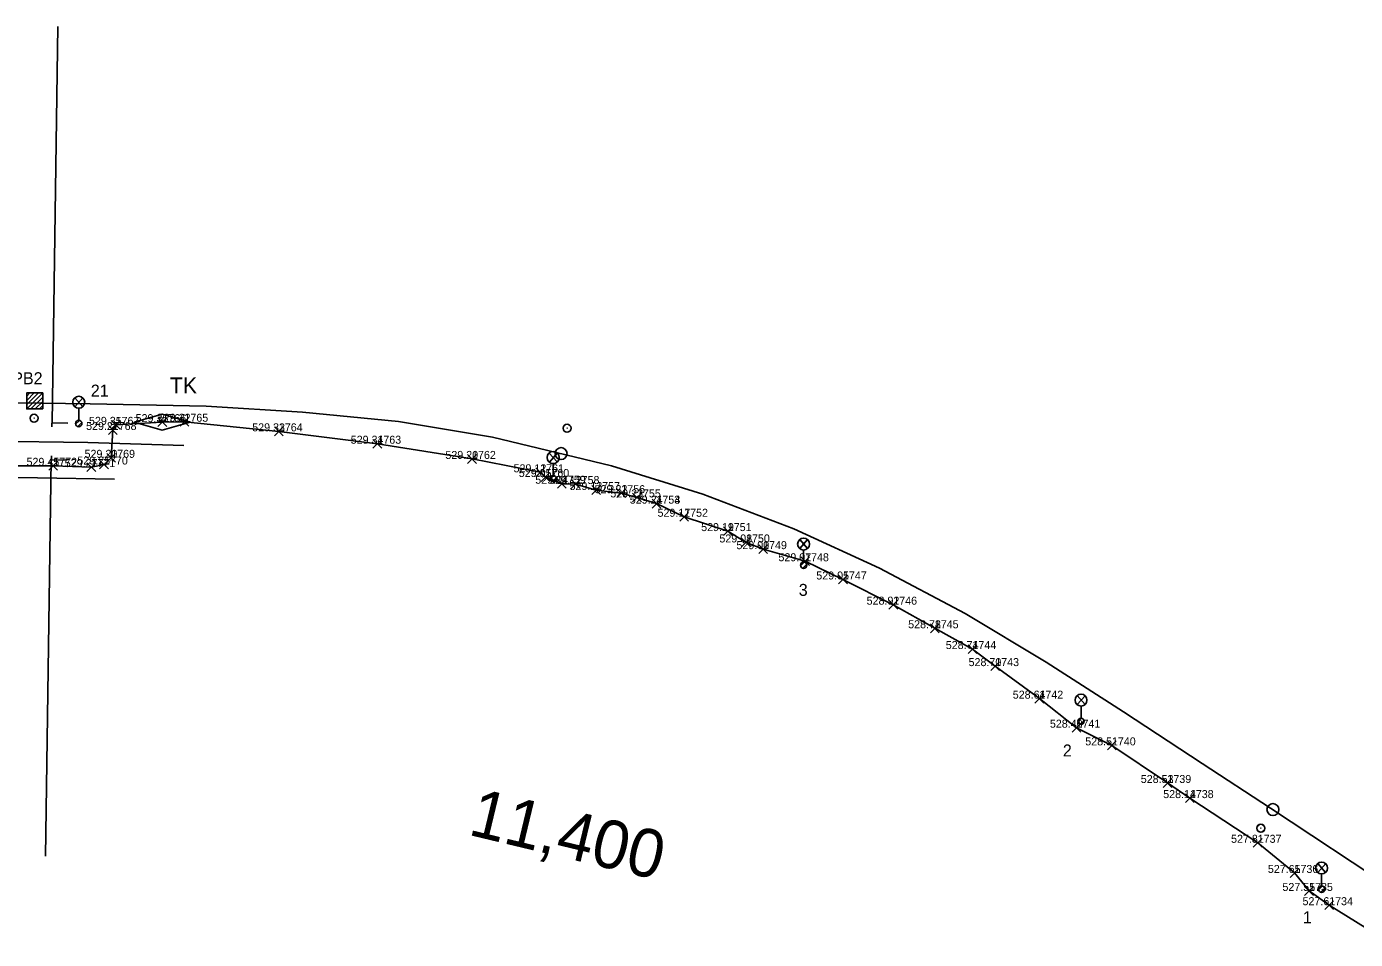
# Model space of a CAD drawing. Extents: x -874058 to -854960, y -10531873 to -1049126.
# Drawn here: x -873748.8 to -873582.7, y -1055503.4 to -1055389.3 of the extents above; entities that cross this region are included whole.
import ezdxf

# ---------------------------------------------------------------- set-up
doc = ezdxf.new("R2010")
doc.units = 0
for name, color, linetype in [('Vrstva 1', 7, 'Continuous'), ('Vrstva 25', 7, 'Continuous'), ('Vrstva 3', 7, 'Continuous'), ('Vrstva 32', 7, 'Continuous'), ('Vrstva 35', 7, 'Continuous'), ('Vrstva 50', 7, 'Continuous'), ('Vrstva 6', 7, 'Continuous'), ('Vrstva 60', 7, 'Continuous'), ('Vrstva 61', 7, 'Continuous'), ('Vrstva 7', 7, 'Continuous')]:
    doc.layers.add(name, color=color, linetype=linetype)

msp = doc.modelspace()

# ---------------------------------------------------------------- linework, layer by layer
at = {"layer": 'Vrstva 1'}
for points in [[(-873927.58, -1055424.84), (-873900.45, -1055425.31), (-873892.13, -1055425.7), (-873880.59, -1055426.63), (-873873.55, -1055427.3), (-873854.79, -1055429.58), (-873843.62, -1055431.39), (-873833.71, -1055432.56), (-873816.9, -1055434.47), (-873807.04, -1055435.55), (-873783.51, -1055438.28), (-873772.32, -1055439.75), (-873753.41, -1055441.11), (-873741.16, -1055441.25), (-873729.15, -1055441.64)], [(-873577.97, -1055497.15), (-873593.34, -1055486.97), (-873601.88, -1055481.39), (-873611.75, -1055474.94), (-873621.41, -1055468.71), (-873631.51, -1055462.63), (-873642.21, -1055456.97), (-873652.94, -1055452.07), (-873664.28, -1055447.72), (-873675.71, -1055444.17), (-873690.6, -1055440.6), (-873702.33, -1055438.64), (-873714.32, -1055437.46), (-873726.38, -1055436.71), (-873740.86, -1055436.45), (-873753.23, -1055436.27)], [(-873737.8, -1055445.87), (-873747.46, -1055445.67), (-873767.6, -1055445.41), (-873858.85, -1055444.62), (-873898.81, -1055444.08), (-873934.67, -1055443.63), (-873987.18, -1055443.07), (-874021.63, -1055442.79), (-874051.6, -1055442.39)]]:
    msp.add_lwpolyline(points, dxfattribs=at)
at = {"layer": 'Vrstva 25'}
for p, q in [((-873742.78, -1055435.68), (-873741.79, -1055436.79)), ((-873742.77, -1055436.81), (-873741.79, -1055435.69)), ((-873742.68, -1055438.97), (-873742.21, -1055438.5)), ((-873742.29, -1055436.99), (-873742.29, -1055438.49)), ((-873742.41, -1055439.27), (-873741.91, -1055438.77)), ((-873683.49, -1055442.58), (-873682.5, -1055443.7)), ((-873683.48, -1055443.71), (-873682.49, -1055442.59)), ((-873683, -1055443.89), (-873683, -1055445.39)), ((-873683.39, -1055445.87), (-873682.92, -1055445.4)), ((-873683.12, -1055446.17), (-873682.62, -1055445.67)), ((-873652.19, -1055453.4), (-873651.2, -1055454.52)), ((-873652.18, -1055454.53), (-873651.2, -1055453.41)), ((-873651.7, -1055454.71), (-873651.7, -1055456.21)), ((-873652.09, -1055456.69), (-873651.62, -1055456.22)), ((-873651.82, -1055456.99), (-873651.32, -1055456.49)), ((-873617.53, -1055472.91), (-873616.54, -1055474.03)), ((-873617.52, -1055474.04), (-873616.54, -1055472.92)), ((-873617.04, -1055474.22), (-873617.04, -1055475.72)), ((-873617.43, -1055476.2), (-873616.96, -1055475.73)), ((-873617.16, -1055476.5), (-873616.66, -1055476)), ((-873587.46, -1055493.9), (-873586.47, -1055495.02)), ((-873587.45, -1055495.03), (-873586.46, -1055493.91)), ((-873586.97, -1055495.21), (-873586.97, -1055496.71)), ((-873587.36, -1055497.19), (-873586.89, -1055496.72)), ((-873587.09, -1055497.49), (-873586.59, -1055496.99))]:
    msp.add_line(p, q, dxfattribs=at)
for centre, radius in [((-873742.29, -1055436.24), 0.749), ((-873742.29, -1055438.89), 0.4), ((-873742.29, -1055438.89), 0.4), ((-873683, -1055443.14), 0.749), ((-873683, -1055445.79), 0.4), ((-873683, -1055445.79), 0.4), ((-873651.7, -1055453.96), 0.749), ((-873651.7, -1055456.61), 0.4), ((-873651.7, -1055456.61), 0.4), ((-873617.04, -1055473.47), 0.749), ((-873617.04, -1055476.12), 0.4), ((-873617.04, -1055476.12), 0.4), ((-873586.97, -1055494.46), 0.749), ((-873586.97, -1055497.11), 0.4), ((-873586.97, -1055497.11), 0.4)]:
    msp.add_circle(centre, radius, dxfattribs=at)
at = {"layer": 'Vrstva 3'}
for p, q in [((-873746.79, -1055435.06), (-873748.79, -1055437.06)), ((-873747.32, -1055435.06), (-873748.79, -1055436.53)), ((-873747.85, -1055435.06), (-873748.79, -1055436)), ((-873748.38, -1055435.06), (-873748.79, -1055435.47)), ((-873746.79, -1055435.59), (-873748.26, -1055437.06)), ((-873746.79, -1055436.12), (-873747.73, -1055437.06)), ((-873746.79, -1055436.65), (-873747.2, -1055437.06))]:
    msp.add_line(p, q, dxfattribs=at)
msp.add_lwpolyline([(-873746.79, -1055437.06), (-873748.79, -1055437.06), (-873748.79, -1055435.06), (-873746.79, -1055435.06)], close=True, dxfattribs=at)
msp.add_lwpolyline([(-873746.79, -1055437.06), (-873748.79, -1055437.06), (-873748.79, -1055435.06), (-873746.79, -1055435.06)], close=True, dxfattribs=at)
msp.add_lwpolyline([(-873746.79, -1055437.06), (-873748.79, -1055437.06), (-873748.79, -1055435.06), (-873746.79, -1055435.06), (-873746.79, -1055437.06)], dxfattribs=at)
msp.add_lwpolyline([(-873746.79, -1055437.06), (-873748.79, -1055437.06), (-873748.79, -1055435.06), (-873746.79, -1055435.06), (-873746.79, -1055437.06)], dxfattribs=at)
at = {"layer": 'Vrstva 32'}
for points in [[(-873735.35, -1055438.72), (-873731.85, -1055437.72), (-873728.35, -1055438.72), (-873731.85, -1055439.72), (-873735.35, -1055438.72)], [(-873751.74, -1055444.2), (-873745.48, -1055444.18), (-873740.71, -1055444.34), (-873739.13, -1055444.02), (-873738.23, -1055443.18), (-873738.04, -1055439.7), (-873737.68, -1055439.06), (-873731.85, -1055438.72), (-873729.08, -1055438.67), (-873717.28, -1055439.87), (-873704.97, -1055441.42), (-873693.14, -1055443.32), (-873684.62, -1055444.99), (-873683.97, -1055445.58), (-873681.91, -1055446.42), (-873680.19, -1055446.46), (-873677.63, -1055447.21), (-873674.49, -1055447.6), (-873672.53, -1055448.13), (-873670.1, -1055448.91)], [(-873579.12, -1055503.39), (-873586.03, -1055499.11), (-873588.54, -1055497.33), (-873590.36, -1055495.08), (-873594.96, -1055491.31), (-873603.44, -1055485.72), (-873606.24, -1055483.83), (-873613.18, -1055479.13), (-873617.6, -1055476.92), (-873622.24, -1055473.29), (-873627.76, -1055469.22), (-873630.61, -1055467.09), (-873635.31, -1055464.49), (-873640.5, -1055461.54), (-873646.79, -1055458.39), (-873651.52, -1055456.11), (-873656.77, -1055454.6), (-873658.9, -1055453.76), (-873661.18, -1055452.34), (-873666.63, -1055450.55), (-873670.1, -1055448.91)]]:
    msp.add_lwpolyline(points, dxfattribs=at)
at = {"layer": 'Vrstva 35'}
msp.add_lwpolyline([(-873738.23, -1055443.18), (-873738.04, -1055439.7)], dxfattribs=at)
at = {"layer": 'Vrstva 50'}
msp.add_line((-873747.92, -1055438.23), (-873747.82, -1055438.23), dxfattribs=at)
msp.add_circle((-873747.87, -1055438.23), 0.5, dxfattribs=at)
at = {"layer": 'Vrstva 6'}
for p, q in [((-873744.9, -1055389.27), (-873745.62, -1055438.79)), ((-873745.61, -1055438.29), (-873745.63, -1055439.29)), ((-873743.64, -1055438.84), (-873745.62, -1055438.79)), ((-873745.72, -1055443.44), (-873746.44, -1055492.96)), ((-873745.71, -1055442.94), (-873745.73, -1055443.94)), ((-873743.74, -1055443.49), (-873745.72, -1055443.44))]:
    msp.add_line(p, q, dxfattribs=at)
at = {"layer": 'Vrstva 60'}
for p, q in [((-873738.23, -1055439.61), (-873737.13, -1055438.51)), ((-873737.13, -1055439.61), (-873738.23, -1055438.51)), ((-873732.4, -1055439.27), (-873731.3, -1055438.17)), ((-873731.3, -1055439.27), (-873732.4, -1055438.17)), ((-873729.63, -1055439.22), (-873728.53, -1055438.12)), ((-873728.53, -1055439.22), (-873729.63, -1055438.12)), ((-873738.59, -1055440.25), (-873737.49, -1055439.15)), ((-873737.49, -1055440.25), (-873738.59, -1055439.15)), ((-873717.83, -1055440.42), (-873716.73, -1055439.32)), ((-873716.73, -1055440.42), (-873717.83, -1055439.32)), ((-873705.52, -1055441.97), (-873704.42, -1055440.87)), ((-873704.42, -1055441.97), (-873705.52, -1055440.87)), ((-873739.68, -1055444.57), (-873738.58, -1055443.47)), ((-873738.58, -1055444.57), (-873739.68, -1055443.47)), ((-873738.78, -1055443.73), (-873737.68, -1055442.63)), ((-873737.68, -1055443.73), (-873738.78, -1055442.63)), ((-873693.69, -1055443.87), (-873692.59, -1055442.77)), ((-873692.59, -1055443.87), (-873693.69, -1055442.77)), ((-873746.03, -1055444.73), (-873744.93, -1055443.63)), ((-873744.93, -1055444.73), (-873746.03, -1055443.63)), ((-873741.26, -1055444.89), (-873740.16, -1055443.79)), ((-873740.16, -1055444.89), (-873741.26, -1055443.79)), ((-873685.17, -1055445.54), (-873684.07, -1055444.44)), ((-873684.07, -1055445.54), (-873685.17, -1055444.44)), ((-873684.52, -1055446.13), (-873683.42, -1055445.03)), ((-873683.42, -1055446.13), (-873684.52, -1055445.03)), ((-873682.46, -1055446.97), (-873681.36, -1055445.87)), ((-873681.36, -1055446.97), (-873682.46, -1055445.87)), ((-873680.74, -1055447.01), (-873679.64, -1055445.91)), ((-873679.64, -1055447.01), (-873680.74, -1055445.91)), ((-873678.18, -1055447.76), (-873677.08, -1055446.66)), ((-873677.08, -1055447.76), (-873678.18, -1055446.66)), ((-873675.04, -1055448.15), (-873673.94, -1055447.05)), ((-873673.94, -1055448.15), (-873675.04, -1055447.05)), ((-873673.08, -1055448.68), (-873671.98, -1055447.58)), ((-873671.98, -1055448.68), (-873673.08, -1055447.58)), ((-873670.65, -1055449.46), (-873669.55, -1055448.36)), ((-873669.55, -1055449.46), (-873670.65, -1055448.36)), ((-873670.65, -1055449.46), (-873669.55, -1055448.36)), ((-873669.55, -1055449.46), (-873670.65, -1055448.36)), ((-873667.18, -1055451.1), (-873666.08, -1055450)), ((-873666.08, -1055451.1), (-873667.18, -1055450)), ((-873661.73, -1055452.89), (-873660.63, -1055451.79)), ((-873660.63, -1055452.89), (-873661.73, -1055451.79)), ((-873659.45, -1055454.31), (-873658.35, -1055453.21)), ((-873658.35, -1055454.31), (-873659.45, -1055453.21)), ((-873657.32, -1055455.15), (-873656.22, -1055454.05)), ((-873656.22, -1055455.15), (-873657.32, -1055454.05)), ((-873652.07, -1055456.66), (-873650.97, -1055455.56)), ((-873650.97, -1055456.66), (-873652.07, -1055455.56)), ((-873647.34, -1055458.94), (-873646.24, -1055457.84)), ((-873646.24, -1055458.94), (-873647.34, -1055457.84)), ((-873641.05, -1055462.09), (-873639.95, -1055460.99)), ((-873639.95, -1055462.09), (-873641.05, -1055460.99)), ((-873635.86, -1055465.04), (-873634.76, -1055463.94)), ((-873634.76, -1055465.04), (-873635.86, -1055463.94)), ((-873631.16, -1055467.64), (-873630.06, -1055466.54)), ((-873630.06, -1055467.64), (-873631.16, -1055466.54)), ((-873628.31, -1055469.77), (-873627.21, -1055468.67)), ((-873627.21, -1055469.77), (-873628.31, -1055468.67)), ((-873622.79, -1055473.84), (-873621.69, -1055472.74)), ((-873621.69, -1055473.84), (-873622.79, -1055472.74)), ((-873618.15, -1055477.47), (-873617.05, -1055476.37)), ((-873617.05, -1055477.47), (-873618.15, -1055476.37)), ((-873613.73, -1055479.68), (-873612.63, -1055478.58)), ((-873612.63, -1055479.68), (-873613.73, -1055478.58)), ((-873606.79, -1055484.38), (-873605.69, -1055483.28)), ((-873605.69, -1055484.38), (-873606.79, -1055483.28)), ((-873603.99, -1055486.27), (-873602.89, -1055485.17)), ((-873602.89, -1055486.27), (-873603.99, -1055485.17)), ((-873595.51, -1055491.86), (-873594.41, -1055490.76)), ((-873594.41, -1055491.86), (-873595.51, -1055490.76)), ((-873590.91, -1055495.63), (-873589.81, -1055494.53)), ((-873589.81, -1055495.63), (-873590.91, -1055494.53)), ((-873589.09, -1055497.88), (-873587.99, -1055496.78)), ((-873587.99, -1055497.88), (-873589.09, -1055496.78)), ((-873586.58, -1055499.66), (-873585.48, -1055498.56)), ((-873585.48, -1055499.66), (-873586.58, -1055498.56))]:
    msp.add_line(p, q, dxfattribs=at)
at = {"layer": 'Vrstva 7'}
for p, q in [((-873681.31, -1055439.48), (-873681.21, -1055439.48)), ((-873594.63, -1055489.48), (-873594.53, -1055489.48)), ((-873594.61, -1055489.49), (-873594.51, -1055489.49))]:
    msp.add_line(p, q, dxfattribs=at)
for centre, radius in [((-873681.26, -1055439.48), 0.5), ((-873682.02, -1055442.66), 0.75), ((-873593.05, -1055487.16), 0.75), ((-873594.58, -1055489.48), 0.5), ((-873594.56, -1055489.49), 0.5)]:
    msp.add_circle(centre, radius, dxfattribs=at)

# ---------------------------------------------------------------- texts
at = {"layer": 'Vrstva 25'}
for s, p in [('21', (-873740.78, -1055435.53)), ('3', (-873652.31, -1055460.44)), ('2', (-873619.31, -1055480.52)), ('1', (-873589.31, -1055501.37))]:
    msp.add_text(s, height=1.5, dxfattribs=at).set_placement(p)
at = {"layer": 'Vrstva 3'}
msp.add_text('TPB2', height=1.5, dxfattribs=at).set_placement((-873751.82, -1055433.98))
at = {"layer": 'Vrstva 32'}
msp.add_text('TK', height=2, dxfattribs=at).set_placement((-873730.92, -1055435.13))
at = {"layer": 'Vrstva 60'}
for s, p in [('1767', (-873737.68, -1055439.06)), ('1766', (-873731.85, -1055438.72)), ('1765', (-873729.08, -1055438.67)), ('1768', (-873738.04, -1055439.7)), ('1764', (-873717.28, -1055439.87)), ('1763', (-873704.97, -1055441.42)), ('1772', (-873745.48, -1055444.18)), ('1771', (-873740.71, -1055444.34)), ('1770', (-873739.13, -1055444.02)), ('1769', (-873738.23, -1055443.18)), ('1762', (-873693.14, -1055443.32)), ('1761', (-873684.62, -1055444.99)), ('1760', (-873683.97, -1055445.58)), ('1759', (-873681.91, -1055446.42)), ('1758', (-873680.19, -1055446.46)), ('1757', (-873677.63, -1055447.21)), ('1756', (-873674.49, -1055447.6)), ('1755', (-873672.53, -1055448.13)), ('1753', (-873670.1, -1055448.91)), ('1754', (-873670.1, -1055448.91)), ('1752', (-873666.63, -1055450.55)), ('1751', (-873661.18, -1055452.34)), ('1750', (-873658.9, -1055453.76)), ('1749', (-873656.77, -1055454.6)), ('1748', (-873651.52, -1055456.11)), ('1747', (-873646.79, -1055458.39)), ('1746', (-873640.5, -1055461.54)), ('1745', (-873635.31, -1055464.49)), ('1744', (-873630.61, -1055467.09)), ('1743', (-873627.76, -1055469.22)), ('1742', (-873622.24, -1055473.29)), ('1741', (-873617.6, -1055476.92)), ('1740', (-873613.18, -1055479.13)), ('1739', (-873606.24, -1055483.83)), ('1738', (-873603.44, -1055485.72)), ('1737', (-873594.96, -1055491.31)), ('1736', (-873590.36, -1055495.08)), ('1735', (-873588.54, -1055497.33)), ('1734', (-873586.03, -1055499.11))]:
    msp.add_text(s, height=1, dxfattribs=at).set_placement(p)
at = {"layer": 'Vrstva 61'}
for s, p in [('529.35 ', (-873741.01, -1055439.06)), ('529.35 ', (-873735.18, -1055438.72)), ('529.32 ', (-873732.41, -1055438.67)), ('529.27 ', (-873741.37, -1055439.7)), ('529.33 ', (-873720.61, -1055439.87)), ('529.34 ', (-873708.3, -1055441.42)), ('529.45 ', (-873748.81, -1055444.18)), ('529.27 ', (-873744.04, -1055444.34)), ('529.25 ', (-873742.46, -1055444.02)), ('529.20 ', (-873741.56, -1055443.18)), ('529.20 ', (-873696.47, -1055443.32)), ('529.12 ', (-873687.95, -1055444.99)), ('529.05 ', (-873687.3, -1055445.58)), ('529.04 ', (-873685.24, -1055446.42)), ('529.12 ', (-873683.52, -1055446.46)), ('529.13 ', (-873680.96, -1055447.21)), ('529.22 ', (-873677.82, -1055447.6)), ('529.23 ', (-873675.86, -1055448.13)), ('529.24 ', (-873673.43, -1055448.91)), ('529.24 ', (-873673.43, -1055448.91)), ('529.17 ', (-873669.96, -1055450.55)), ('529.19 ', (-873664.51, -1055452.34)), ('529.08 ', (-873662.23, -1055453.76)), ('529.00 ', (-873660.1, -1055454.6)), ('529.07 ', (-873654.85, -1055456.11)), ('529.05 ', (-873650.12, -1055458.39)), ('528.92 ', (-873643.83, -1055461.54)), ('528.78 ', (-873638.64, -1055464.49)), ('528.74 ', (-873633.94, -1055467.09)), ('528.70 ', (-873631.09, -1055469.22)), ('528.64 ', (-873625.57, -1055473.29)), ('528.40 ', (-873620.93, -1055476.92)), ('528.51 ', (-873616.51, -1055479.13)), ('528.53 ', (-873609.57, -1055483.83)), ('528.14 ', (-873606.77, -1055485.72)), ('527.81 ', (-873598.29, -1055491.31)), ('527.65 ', (-873593.69, -1055495.08)), ('527.55 ', (-873591.87, -1055497.33)), ('527.61 ', (-873589.36, -1055499.11))]:
    msp.add_text(s, height=1, dxfattribs=at).set_placement(p)
at = {"layer": 'Vrstva 7'}
msp.add_text('11,400', height=6, rotation=346.5179, dxfattribs=at).set_placement((-873693.77, -1055490.27))

doc.saveas('drawing.dxf')
